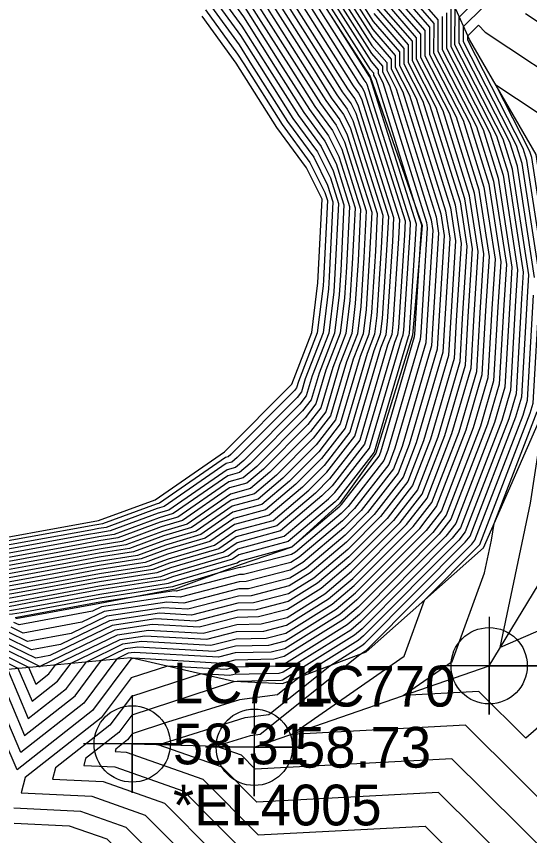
# Model space of a CAD drawing. Extents: x 2188792 to 2191981, y 386090 to 389710.
# Drawn here: x 2189631.5 to 2189663.1, y 387097.8 to 387148.1 of the extents above; entities that cross this region are included whole.
import ezdxf

# ---------------------------------------------------------------- set-up
doc = ezdxf.new("R2010")
doc.units = 0
for name, color, linetype in [('DTM Contours Major', 7, 'Continuous'), ('DTM Contours Minor', 7, 'Continuous'), ('Exist DTM Breakline', 7, 'Continuous'), ('Exist DTM Breakline Cogo Comment', 7, 'Continuous'), ('Exist DTM Breakline Cogo Elevation', 7, 'Continuous'), ('Exist DTM Breakline Cogo Number', 7, 'Continuous'), ('Exist DTM Breakline Cogo Point CELL', 7, 'Continuous'), ('PH Exist DTM Breakline', 7, 'Continuous')]:
    doc.layers.add(name, color=color, linetype=linetype)

msp = doc.modelspace()

# ---------------------------------------------------------------- linework, layer by layer
at = {"layer": 'DTM Contours Major'}
for points in [[(2189647.605, 387154.888), (2189653.356, 387145.845), (2189654.035, 387145.062), (2189654.034, 387144.713), (2189654.465, 387143.873), (2189657.034, 387135.639), (2189657.136, 387134.979), (2189656.746, 387128.839), (2189656.703, 387128.084), (2189654.801, 387121.603), (2189654.415, 387120.6), (2189652.316, 387117.904), (2189651.57, 387117.157), (2189648.909, 387114.911), (2189648.399, 387114.593), (2189645.491, 387113.849), (2189645.247, 387113.844), (2189641.36, 387112.838), (2189641.227, 387112.846), (2189639.101, 387112.531), (2189636.658, 387112.15), (2189631.567, 387111.212)], [(2189646.36, 387153.857), (2189652.258, 387144.532), (2189652.567, 387144.044), (2189652.792, 387143.738), (2189652.911, 387143.499), (2189655.42, 387135.563), (2189655.376, 387134.685), (2189655.01, 387129.027), (2189654.955, 387128.574), (2189654.773, 387128.103), (2189652.933, 387121.863), (2189650.94, 387119.302), (2189650.314, 387118.674), (2189647.766, 387116.527), (2189645.094, 387115.801), (2189644.261, 387115.224), (2189640.999, 387114.263), (2189640.165, 387113.955), (2189636.641, 387113.405), (2189632.825, 387112.703), (2189630.597, 387112.3)], [(2189645.921, 387150.976), (2189649.847, 387144.77), (2189650.886, 387143.129), (2189651.642, 387142.096), (2189652.045, 387141.291), (2189653.714, 387136.01), (2189653.599, 387133.704), (2189653.356, 387129.938), (2189653.195, 387128.618), (2189652.663, 387127.247), (2189651.438, 387123.094), (2189650.112, 387121.39), (2189648.312, 387119.583), (2189646.616, 387118.154), (2189644.838, 387117.671), (2189642.859, 387116.301), (2189640.688, 387115.661), (2189638.969, 387115.027), (2189636.623, 387114.661), (2189634.084, 387114.193), (2189629.733, 387113.407)], [(2189630.325, 387107.976), (2189632.033, 387103.97), (2189635.141, 387106.401), (2189636.772, 387108.588), (2189638.247, 387109.301), (2189638.986, 387109.41), (2189643.716, 387109.139), (2189645.006, 387109.473), (2189647.041, 387109.517), (2189648.064, 387109.779), (2189651.176, 387111.72), (2189652.376, 387112.732), (2189656.319, 387116.686), (2189657.357, 387118.019), (2189659.174, 387122.737), (2189660.169, 387126.128), (2189660.393, 387130.046), (2189660.605, 387133.372), (2189659.974, 387137.458), (2189658.576, 387141.941), (2189656.654, 387145.687), (2189656.657, 387147.247), (2189653.628, 387150.741)], [(2189644.006, 387150.136), (2189645.482, 387148.095), (2189647.435, 387145.008), (2189649.205, 387142.213), (2189650.493, 387140.455), (2189651.178, 387139.083), (2189652.009, 387136.456), (2189651.822, 387132.723), (2189651.701, 387130.85), (2189651.435, 387128.662), (2189650.553, 387126.391), (2189649.944, 387124.325), (2189649.284, 387123.477), (2189646.311, 387120.493), (2189645.467, 387119.782), (2189644.583, 387119.542), (2189641.458, 387117.378), (2189640.378, 387117.06), (2189637.772, 387116.098), (2189636.606, 387115.916), (2189635.343, 387115.684), (2189628.869, 387114.514)], [(2189653.492, 387148.293), (2189655.346, 387146.154), (2189655.344, 387145.2), (2189656.52, 387142.907), (2189658.504, 387136.548), (2189658.87, 387134.176), (2189658.57, 387129.442), (2189658.436, 387127.106), (2189656.988, 387122.17), (2189655.886, 387119.309), (2189654.317, 387117.295), (2189651.973, 387114.945), (2189650.042, 387113.315), (2189648.231, 387112.186), (2189646.266, 387111.683), (2189645.126, 387111.658), (2189642.538, 387110.989), (2189640.107, 387111.128), (2189637.427, 387110.731), (2189633.589, 387108.875), (2189632.724, 387108.712), (2189630.704, 387109.708)], [(2189657.968, 387148.339), (2189657.964, 387146.175), (2189660.631, 387140.974), (2189661.444, 387138.368), (2189662.339, 387132.568), (2189662.217, 387130.649), (2189661.903, 387125.151), (2189661.361, 387123.304), (2189658.829, 387116.729), (2189658.32, 387116.076), (2189652.779, 387110.52), (2189652.31, 387110.124), (2189647.897, 387107.371), (2189647.815, 387107.351), (2189645.1, 387107.292), (2189644.897, 387107.265), (2189644.755, 387107.221), (2189638.621, 387105.219), (2189637.821, 387104.147), (2189635.783, 387102.552), (2189635.675, 387102.136), (2189637.572, 387102.047), (2189641.816, 387100.554), (2189646.489, 387095.847)], [(2189659.274, 387146.662), (2189659.274, 387146.923), (2189659.943, 387147.587), (2189660.338, 387147.144), (2189666.223, 387143.262)], [(2189664.073, 387131.764), (2189662.914, 387139.278), (2189662.687, 387140.008), (2189659.274, 387146.662)], [(2189665.225, 387105.878), (2189662.851, 387103.796), (2189659.953, 387106.663), (2189655.312, 387106.421), (2189658.316, 387108.505), (2189660.313, 387113.953), (2189660.737, 387115.963), (2189660.891, 387116.975), (2189663.547, 387123.87)], [(2189631.567, 387111.212), (2189631.461, 387111.193)]]:
    msp.add_lwpolyline(points, dxfattribs=at)
at = {"layer": 'DTM Contours Minor'}
for points in [[(2189647.266, 387154.889), (2189653.329, 387145.355), (2189653.772, 387144.844), (2189653.772, 387144.615), (2189654.053, 387144.066), (2189656.74, 387135.457), (2189656.789, 387135.14), (2189656.381, 387128.718), (2189656.356, 387128.279), (2189654.364, 387121.49), (2189654.121, 387120.858), (2189651.915, 387118.026), (2189651.49, 387117.599), (2189648.682, 387115.23), (2189648.432, 387115.075), (2189645.336, 387114.282), (2189645.271, 387114.281), (2189643.923, 387113.932), (2189641.248, 387113.144), (2189641.122, 387113.098), (2189636.654, 387112.401), (2189631.819, 387111.51), (2189631.289, 387111.414), (2189623.717, 387110.905)], [(2189648.963, 387154.882), (2189653.465, 387147.803), (2189655.083, 387145.936), (2189655.082, 387145.103), (2189656.109, 387143.1), (2189658.21, 387136.366), (2189658.523, 387134.336), (2189658.205, 387129.322), (2189658.089, 387127.302), (2189656.551, 387122.057), (2189655.592, 387119.567), (2189653.917, 387117.417), (2189651.893, 387115.387), (2189649.816, 387113.635), (2189648.265, 387112.667), (2189646.111, 387112.116), (2189645.15, 387112.095), (2189642.302, 387111.358), (2189640.331, 387111.472), (2189637.263, 387111.017), (2189634.245, 387109.558), (2189632.467, 387109.223), (2189630.873, 387110.009)], [(2189648.624, 387154.884), (2189653.438, 387147.314), (2189654.821, 387145.717), (2189654.82, 387145.005), (2189655.698, 387143.293), (2189657.916, 387136.184), (2189658.177, 387134.497), (2189657.84, 387129.201), (2189657.743, 387127.497), (2189656.113, 387121.943), (2189655.298, 387119.825), (2189653.517, 387117.539), (2189651.812, 387115.83), (2189649.589, 387113.954), (2189648.298, 387113.149), (2189645.956, 387112.549), (2189645.174, 387112.533), (2189642.067, 387111.728), (2189640.555, 387111.815), (2189637.098, 387111.303), (2189634.902, 387110.241), (2189632.211, 387109.733), (2189631.041, 387110.31)], [(2189648.284, 387154.885), (2189653.41, 387146.824), (2189654.559, 387145.499), (2189654.558, 387144.908), (2189655.287, 387143.486), (2189657.622, 387136.002), (2189657.83, 387134.658), (2189657.475, 387129.08), (2189657.396, 387127.693), (2189655.676, 387121.83), (2189655.003, 387120.083), (2189653.116, 387117.66), (2189651.732, 387116.272), (2189649.362, 387114.273), (2189648.332, 387113.63), (2189645.801, 387112.983), (2189645.198, 387112.97), (2189641.831, 387112.098), (2189640.779, 387112.159), (2189636.934, 387111.589), (2189635.558, 387110.923), (2189631.954, 387110.244), (2189631.209, 387110.611)], [(2189647.945, 387154.886), (2189653.383, 387146.334), (2189654.297, 387145.281), (2189654.296, 387144.81), (2189654.876, 387143.68), (2189657.328, 387135.82), (2189657.483, 387134.819), (2189657.111, 387128.959), (2189657.049, 387127.888), (2189655.239, 387121.717), (2189654.709, 387120.341), (2189652.716, 387117.782), (2189651.651, 387116.714), (2189649.136, 387114.592), (2189648.365, 387114.112), (2189645.646, 387113.416), (2189645.223, 387113.407), (2189641.596, 387112.468), (2189641.003, 387112.502), (2189636.77, 387111.875), (2189636.215, 387111.606), (2189631.697, 387110.754), (2189631.378, 387110.912)], [(2189648.455, 387115.55), (2189648.778, 387115.822), (2189651.409, 387118.042), (2189651.515, 387118.148), (2189653.826, 387121.116), (2189653.927, 387121.377), (2189656.009, 387128.475), (2189656.016, 387128.597), (2189656.37, 387134.17), (2189656.442, 387135.273), (2189656.443, 387135.295), (2189656.214, 387136.018), (2189653.642, 387144.259), (2189653.51, 387144.518), (2189653.51, 387144.625), (2189653.301, 387144.866), (2189646.927, 387154.891)], [(2189630.77, 387112.079), (2189632.574, 387112.405), (2189636.644, 387113.154), (2189640.404, 387113.741), (2189641.061, 387113.983), (2189644.541, 387115.008), (2189645.145, 387115.426), (2189647.996, 387116.201), (2189650.714, 387118.492), (2189651.106, 387118.885), (2189653.232, 387121.616), (2189655.195, 387128.274), (2189655.307, 387128.565), (2189655.341, 387128.845), (2189655.731, 387134.881), (2189655.761, 387135.474), (2189653.085, 387143.94), (2189653.022, 387144.066), (2189652.903, 387144.227), (2189652.741, 387144.484), (2189646.448, 387154.433)], [(2189646.272, 387153.281), (2189651.776, 387144.579), (2189652.231, 387143.861), (2189652.562, 387143.409), (2189652.738, 387143.057), (2189655.078, 387135.653), (2189655.02, 387134.489), (2189654.679, 387129.209), (2189654.603, 387128.582), (2189654.351, 387127.932), (2189652.634, 387122.109), (2189650.775, 387119.72), (2189649.914, 387118.856), (2189647.536, 387116.852), (2189645.043, 387116.175), (2189643.981, 387115.439), (2189640.937, 387114.543), (2189639.926, 387114.169), (2189636.637, 387113.656), (2189633.077, 387113.001), (2189630.425, 387112.521)], [(2189630.252, 387112.743), (2189633.329, 387113.299), (2189636.634, 387113.908), (2189639.686, 387114.384), (2189640.875, 387114.822), (2189643.7, 387115.655), (2189644.992, 387116.549), (2189647.306, 387117.178), (2189649.513, 387119.038), (2189650.609, 387120.137), (2189652.335, 387122.355), (2189653.929, 387127.761), (2189654.251, 387128.591), (2189654.349, 387129.391), (2189654.665, 387134.292), (2189654.737, 387135.742), (2189652.565, 387142.616), (2189652.332, 387143.081), (2189651.895, 387143.678), (2189651.294, 387144.627), (2189646.185, 387152.705)], [(2189653.71, 387152.209), (2189657.443, 387147.902), (2189657.44, 387145.98), (2189659.809, 387141.361), (2189660.856, 387138.004), (2189661.645, 387132.889), (2189661.487, 387130.408), (2189661.209, 387125.542), (2189660.486, 387123.077), (2189658.24, 387117.245), (2189657.52, 387116.32), (2189652.618, 387111.405), (2189651.856, 387110.762), (2189647.964, 387108.334), (2189647.505, 387108.217), (2189644.933, 387108.161), (2189644.422, 387108.029), (2189640.823, 387108.236), (2189638.582, 387107.504), (2189636.749, 387105.049), (2189632.079, 387101.395), (2189631.831, 387100.44), (2189636.178, 387100.236), (2189639.448, 387099.085), (2189646.672, 387091.811)], [(2189658.75, 387146.467), (2189658.753, 387148.074), (2189662.88, 387152.179)], [(2189646.097, 387152.129), (2189650.811, 387144.675), (2189651.558, 387143.495), (2189652.102, 387142.753), (2189652.391, 387142.174), (2189654.396, 387135.831), (2189654.309, 387134.096), (2189654.018, 387129.574), (2189653.899, 387128.6), (2189653.507, 387127.589), (2189652.036, 387122.601), (2189650.444, 387120.555), (2189649.113, 387119.22), (2189647.076, 387117.503), (2189644.94, 387116.923), (2189643.42, 387115.87), (2189640.813, 387115.102), (2189639.447, 387114.598), (2189636.63, 387114.159), (2189633.581, 387113.597), (2189630.079, 387112.964)], [(2189653.683, 387151.72), (2189657.181, 387147.684), (2189657.178, 387145.882), (2189659.398, 387141.554), (2189660.562, 387137.822), (2189661.298, 387133.05), (2189661.123, 387130.287), (2189660.863, 387125.737), (2189660.049, 387122.963), (2189657.946, 387117.503), (2189657.119, 387116.442), (2189652.538, 387111.847), (2189651.629, 387111.081), (2189647.997, 387108.816), (2189647.351, 387108.65), (2189644.957, 387108.598), (2189644.187, 387108.399), (2189638.757, 387108.711), (2189638.562, 387108.647), (2189636.213, 387105.5), (2189631.571, 387101.868), (2189630.764, 387103.763)], [(2189653.655, 387151.23), (2189656.919, 387147.465), (2189656.916, 387145.785), (2189658.987, 387141.747), (2189660.268, 387137.64), (2189660.951, 387133.211), (2189660.758, 387130.167), (2189660.516, 387125.933), (2189659.612, 387122.85), (2189657.652, 387117.761), (2189656.719, 387116.564), (2189652.457, 387112.29), (2189651.403, 387111.4), (2189648.03, 387109.297), (2189647.196, 387109.084), (2189644.981, 387109.036), (2189643.951, 387108.769), (2189638.762, 387109.067), (2189638.411, 387109.015), (2189637.711, 387108.676), (2189635.677, 387105.951), (2189631.802, 387102.919), (2189629.744, 387107.748)], [(2189646.009, 387151.552), (2189650.329, 387144.722), (2189651.222, 387143.312), (2189651.872, 387142.424), (2189652.218, 387141.732), (2189654.055, 387135.921), (2189653.954, 387133.9), (2189653.687, 387129.756), (2189653.547, 387128.609), (2189653.085, 387127.418), (2189651.737, 387122.847), (2189650.278, 387120.972), (2189648.713, 387119.401), (2189646.846, 387117.829), (2189644.889, 387117.297), (2189643.14, 387116.086), (2189640.751, 387115.382), (2189639.208, 387114.812), (2189636.627, 387114.41), (2189633.832, 387113.895), (2189629.906, 387113.186)], [(2189645.833, 387150.4), (2189649.364, 387144.818), (2189650.55, 387142.946), (2189651.412, 387141.768), (2189651.871, 387140.849), (2189653.373, 387136.099), (2189653.243, 387133.508), (2189653.025, 387130.121), (2189652.843, 387128.626), (2189652.241, 387127.076), (2189651.139, 387123.34), (2189649.947, 387121.807), (2189647.912, 387119.765), (2189646.387, 387118.48), (2189644.787, 387118.045), (2189642.579, 387116.516), (2189640.626, 387115.941), (2189638.729, 387115.241), (2189636.62, 387114.912), (2189634.336, 387114.491), (2189629.561, 387113.628)], [(2189630.977, 387108.038), (2189632.263, 387105.02), (2189634.604, 387106.852), (2189635.833, 387108.499), (2189638.083, 387109.587), (2189639.211, 387109.754), (2189643.48, 387109.509), (2189645.03, 387109.91), (2189646.886, 387109.95), (2189648.097, 387110.26), (2189650.949, 387112.039), (2189652.296, 387113.175), (2189655.918, 387116.807), (2189657.063, 387118.277), (2189658.737, 387122.623), (2189659.823, 387126.324), (2189660.028, 387129.925), (2189660.258, 387133.533), (2189659.68, 387137.276), (2189658.164, 387142.134), (2189656.392, 387145.59), (2189656.395, 387147.028), (2189653.601, 387150.251)], [(2189643.793, 387149.733), (2189645.394, 387147.519), (2189646.952, 387145.056), (2189648.869, 387142.03), (2189650.263, 387140.126), (2189651.005, 387138.642), (2189651.667, 387136.546), (2189651.466, 387132.527), (2189651.37, 387131.032), (2189651.083, 387128.67), (2189650.131, 387126.219), (2189649.645, 387124.571), (2189649.118, 387123.895), (2189645.91, 387120.675), (2189645.237, 387120.108), (2189644.531, 387119.916), (2189641.177, 387117.593), (2189640.316, 387117.34), (2189637.533, 387116.313), (2189636.602, 387116.168), (2189635.594, 387115.982), (2189628.697, 387114.735)], [(2189645.746, 387149.824), (2189648.882, 387144.865), (2189650.213, 387142.763), (2189651.182, 387141.44), (2189651.698, 387140.408), (2189653.032, 387136.188), (2189652.888, 387133.312), (2189652.694, 387130.303), (2189652.491, 387128.635), (2189651.819, 387126.904), (2189650.84, 387123.586), (2189649.781, 387122.225), (2189647.512, 387119.947), (2189646.157, 387118.805), (2189644.736, 387118.419), (2189642.299, 387116.732), (2189640.564, 387116.221), (2189638.49, 387115.455), (2189636.616, 387115.163), (2189634.587, 387114.789), (2189629.388, 387113.85)], [(2189630.199, 387108.806), (2189631.629, 387108.101), (2189632.494, 387106.071), (2189634.068, 387107.303), (2189634.895, 387108.41), (2189637.919, 387109.873), (2189639.435, 387110.098), (2189643.245, 387109.879), (2189645.054, 387110.347), (2189646.731, 387110.383), (2189648.131, 387110.742), (2189650.723, 387112.358), (2189652.215, 387113.617), (2189655.518, 387116.929), (2189656.769, 387118.535), (2189658.3, 387122.51), (2189659.476, 387126.519), (2189659.664, 387129.804), (2189659.911, 387133.693), (2189659.386, 387137.094), (2189657.753, 387142.327), (2189656.13, 387145.492), (2189656.132, 387146.81), (2189653.574, 387149.761)], [(2189659.012, 387146.565), (2189659.014, 387147.498), (2189661.412, 387149.883)], [(2189643.58, 387149.33), (2189645.306, 387146.943), (2189646.47, 387145.104), (2189648.532, 387141.847), (2189650.033, 387139.798), (2189650.832, 387138.2), (2189651.326, 387136.635), (2189651.111, 387132.331), (2189651.039, 387131.214), (2189650.731, 387128.679), (2189649.709, 387126.048), (2189649.346, 387124.817), (2189648.953, 387124.312), (2189645.51, 387120.857), (2189645.007, 387120.433), (2189644.48, 387120.29), (2189640.897, 387117.809), (2189640.254, 387117.619), (2189637.294, 387116.527), (2189636.599, 387116.419), (2189635.846, 387116.28), (2189628.524, 387114.957)], [(2189645.658, 387149.248), (2189648.399, 387144.913), (2189649.877, 387142.579), (2189650.952, 387141.111), (2189651.525, 387139.966), (2189652.691, 387136.278), (2189652.532, 387133.115), (2189652.363, 387130.485), (2189652.139, 387128.644), (2189651.397, 387126.733), (2189650.541, 387123.832), (2189649.615, 387122.642), (2189647.111, 387120.129), (2189645.927, 387119.131), (2189644.685, 387118.793), (2189642.018, 387116.947), (2189640.502, 387116.5), (2189638.251, 387115.67), (2189636.613, 387115.414), (2189634.839, 387115.088), (2189629.215, 387114.071)], [(2189630.368, 387109.107), (2189632.281, 387108.163), (2189632.724, 387107.122), (2189633.532, 387107.754), (2189633.956, 387108.322), (2189637.755, 387110.159), (2189639.659, 387110.441), (2189643.009, 387110.249), (2189645.078, 387110.784), (2189646.576, 387110.817), (2189648.164, 387111.223), (2189650.496, 387112.677), (2189652.135, 387114.06), (2189655.118, 387117.051), (2189656.475, 387118.793), (2189657.862, 387122.397), (2189659.129, 387126.715), (2189659.299, 387129.684), (2189659.564, 387133.854), (2189659.092, 387136.912), (2189657.342, 387142.52), (2189655.868, 387145.395), (2189655.87, 387146.591), (2189653.546, 387149.272)], [(2189643.367, 387148.926), (2189645.219, 387146.367), (2189645.988, 387145.151), (2189648.196, 387141.664), (2189649.803, 387139.47), (2189650.658, 387137.759), (2189650.985, 387136.724), (2189650.756, 387132.134), (2189650.708, 387131.397), (2189650.379, 387128.688), (2189649.287, 387125.877), (2189649.047, 387125.063), (2189648.787, 387124.729), (2189645.11, 387121.039), (2189644.778, 387120.759), (2189644.429, 387120.664), (2189640.617, 387118.024), (2189640.191, 387117.899), (2189637.055, 387116.741), (2189636.595, 387116.67), (2189636.098, 387116.578), (2189628.351, 387115.178)], [(2189645.57, 387148.672), (2189647.917, 387144.961), (2189649.541, 387142.396), (2189650.723, 387140.783), (2189651.352, 387139.525), (2189652.35, 387136.367), (2189652.177, 387132.919), (2189652.032, 387130.668), (2189651.787, 387128.653), (2189650.975, 387126.562), (2189650.242, 387124.078), (2189649.45, 387123.06), (2189646.711, 387120.311), (2189645.697, 387119.456), (2189644.634, 387119.168), (2189641.738, 387117.163), (2189640.44, 387116.78), (2189638.012, 387115.884), (2189636.609, 387115.665), (2189635.091, 387115.386), (2189629.042, 387114.293)], [(2189653.519, 387148.782), (2189655.608, 387146.373), (2189655.606, 387145.297), (2189656.931, 387142.713), (2189658.798, 387136.73), (2189659.217, 387134.015), (2189658.934, 387129.563), (2189658.783, 387126.911), (2189657.425, 387122.283), (2189656.18, 387119.051), (2189654.718, 387117.173), (2189652.054, 387114.502), (2189650.269, 387112.996), (2189648.198, 387111.704), (2189646.421, 387111.25), (2189645.102, 387111.221), (2189642.773, 387110.619), (2189639.883, 387110.785), (2189637.591, 387110.445), (2189633.017, 387108.233), (2189632.996, 387108.205), (2189632.955, 387108.172), (2189632.932, 387108.225), (2189630.536, 387109.408)], [(2189643.154, 387148.523), (2189645.131, 387145.791), (2189645.505, 387145.199), (2189647.86, 387141.481), (2189649.573, 387139.141), (2189650.485, 387137.317), (2189650.644, 387136.814), (2189650.4, 387131.938), (2189650.377, 387131.579), (2189650.027, 387128.697), (2189648.865, 387125.706), (2189648.748, 387125.309), (2189648.621, 387125.147), (2189644.709, 387121.221), (2189644.548, 387121.084), (2189644.378, 387121.038), (2189640.336, 387118.24), (2189640.129, 387118.179), (2189636.815, 387116.956), (2189636.592, 387116.921), (2189636.35, 387116.876), (2189628.178, 387115.4)], [(2189658.23, 387148.558), (2189658.226, 387146.272), (2189661.042, 387140.781), (2189661.738, 387138.55), (2189662.686, 387132.407), (2189662.582, 387130.77), (2189662.249, 387124.955), (2189661.798, 387123.417), (2189659.123, 387116.471), (2189658.721, 387115.954), (2189652.86, 387110.078), (2189652.536, 387109.805), (2189648.936, 387107.559), (2189647.578, 387106.475), (2189645.24, 387106.169), (2189640.815, 387104.786), (2189638.641, 387104.076), (2189638.358, 387103.696), (2189637.635, 387103.131), (2189637.597, 387102.983), (2189638.269, 387102.952), (2189642.999, 387101.288), (2189646.398, 387097.865), (2189656.648, 387098.399), (2189674.627, 387080.612)], [(2189662.831, 387148.294), (2189667.63, 387145.128), (2189669.809, 387142.821), (2189680.313, 387132.407), (2189681.081, 387131.605), (2189684.866, 387130.133), (2189689.558, 387120.471), (2189692.997, 387116.023), (2189688.385, 387114.021), (2189671.258, 387102.79), (2189665.795, 387098), (2189659.127, 387104.597), (2189648.448, 387104.04), (2189655.359, 387108.837), (2189656.622, 387112.28), (2189659.922, 387115.589), (2189660.006, 387115.697), (2189663.11, 387123.757), (2189663.289, 387124.369), (2189663.676, 387131.132), (2189663.726, 387131.925), (2189662.62, 387139.096), (2189662.276, 387140.201), (2189659.012, 387146.565)], [(2189658.488, 387146.37), (2189658.492, 387148.65)], [(2189650.88, 387148.142), (2189653.223, 387144.436), (2189653.24, 387144.411), (2189653.252, 387144.394), (2189653.258, 387144.382), (2189656.102, 387135.385), (2189656.086, 387135.077), (2189655.672, 387128.662), (2189655.659, 387128.556), (2189655.617, 387128.446), (2189653.531, 387121.37), (2189651.272, 387118.468), (2189651.115, 387118.31), (2189648.226, 387115.875), (2189645.196, 387115.052), (2189644.822, 387114.793), (2189641.123, 387113.703), (2189640.643, 387113.526), (2189636.648, 387112.903), (2189632.322, 387112.106), (2189630.943, 387111.857)], [(2189657.706, 387148.121), (2189657.702, 387146.077), (2189660.22, 387141.168), (2189661.15, 387138.186), (2189661.992, 387132.729), (2189661.852, 387130.529), (2189661.556, 387125.346), (2189660.923, 387123.19), (2189658.534, 387116.987), (2189657.92, 387116.198), (2189652.699, 387110.963), (2189652.083, 387110.443), (2189647.93, 387107.853), (2189647.66, 387107.784), (2189644.909, 387107.724), (2189644.658, 387107.659), (2189642.889, 387107.761), (2189638.601, 387106.362), (2189637.285, 387104.598), (2189633.931, 387101.974), (2189633.753, 387101.288), (2189636.875, 387101.141), (2189640.632, 387099.819), (2189646.581, 387093.829)], [(2189702.211, 387112.776), (2189694.002, 387103.617), (2189683.326, 387096.616), (2189671.683, 387086.408), (2189657.474, 387100.465), (2189646.307, 387099.883), (2189644.183, 387102.022), (2189640.25, 387103.406), (2189645.583, 387105.072), (2189647.044, 387105.263), (2189650.788, 387108.254), (2189652.763, 387109.485), (2189652.94, 387109.635), (2189659.121, 387115.832), (2189659.417, 387116.213), (2189662.235, 387123.53), (2189662.596, 387124.76), (2189662.946, 387130.891), (2189663.032, 387132.246), (2189662.032, 387138.732), (2189661.453, 387140.588), (2189658.488, 387146.37)], [(2189663.379, 387132.086), (2189662.326, 387138.914), (2189661.864, 387140.395), (2189658.75, 387146.467)], [(2189663.098, 387139.815), (2189660.993, 387143.919), (2189664.817, 387141.396), (2189665.516, 387140.656), (2189670.642, 387135.574), (2189670.784, 387130.948), (2189677.871, 387129.045), (2189685.089, 387119.711), (2189661.269, 387109.37), (2189663.139, 387118.234), (2189664.018, 387123.993), (2189663.993, 387124.157), (2189664.405, 387131.374), (2189664.42, 387131.603), (2189663.208, 387139.46), (2189663.098, 387139.815)], [(2189668.739, 387092.204), (2189658.3, 387102.531), (2189646.216, 387101.901), (2189645.367, 387102.756), (2189643.795, 387103.309), (2189645.926, 387103.976), (2189646.511, 387104.052), (2189652.64, 387108.948), (2189652.99, 387109.166), (2189653.021, 387109.193), (2189659.521, 387115.711), (2189659.711, 387115.955), (2189662.673, 387123.644), (2189662.943, 387124.564), (2189663.311, 387131.012)], [(2189631.116, 387111.636), (2189632.07, 387111.808), (2189636.651, 387112.652), (2189640.883, 387113.312), (2189641.186, 387113.424), (2189645.102, 387114.578), (2189645.247, 387114.678), (2189648.455, 387115.55)], [(2189631.379, 387099.523), (2189635.481, 387099.33), (2189638.265, 387098.351), (2189646.763, 387089.793), (2189653.343, 387090.136), (2189675.534, 387068.182), (2189677.293, 387065.514), (2189673.661, 387049.813), (2189672.535, 387047.306), (2189658.509, 387033.907)], [(2189631.399, 387098.584), (2189634.784, 387098.425), (2189637.081, 387097.617), (2189646.854, 387087.775), (2189652.517, 387088.07), (2189671.614, 387069.177), (2189674.484, 387064.824), (2189671.509, 387051.964), (2189669.647, 387047.819), (2189657.721, 387036.426), (2189645.777, 387026.074)]]:
    msp.add_lwpolyline(points, dxfattribs=at)
at = {"layer": 'Exist DTM Breakline'}
msp.add_lwpolyline([(2189638.652, 387103.449), (2189646.155, 387103.245), (2189660.588, 387108.25), (2189671.434, 387126.078)], dxfattribs=at)
at = {"layer": 'Exist DTM Breakline Cogo Point CELL'}
for points in [[(2189660.588, 387111.25), (2189660.588, 387105.25), (2189660.588, 387108.25), (2189663.588, 387108.25), (2189657.588, 387108.25)], [(2189638.652, 387106.449), (2189638.652, 387100.449), (2189638.652, 387103.449), (2189641.652, 387103.449), (2189635.652, 387103.449)], [(2189646.155, 387106.245), (2189646.155, 387100.245), (2189646.155, 387103.245), (2189649.155, 387103.245), (2189643.155, 387103.245)]]:
    msp.add_lwpolyline(points, dxfattribs=at)
for centre in [(2189660.588, 387108.25), (2189638.652, 387103.449), (2189646.155, 387103.245)]:
    msp.add_circle(centre, 2.344, dxfattribs=at)
at = {"layer": 'PH Exist DTM Breakline'}
for points in [[(2189646.518, 387154.892), (2189653.277, 387144.431), (2189656.469, 387135.289), (2189655.875, 387128.551), (2189653.62, 387121.297), (2189651.383, 387118.188), (2189648.465, 387115.537), (2189645.28, 387114.441), (2189641.292, 387112.945), (2189636.659, 387112.069), (2189631.504, 387111.138)], [(2189629.701, 387107.916), (2189632.967, 387108.229), (2189638.56, 387108.756), (2189644.886, 387107.302), (2189647.882, 387107.164), (2189653.038, 387109.098), (2189660.239, 387115.492), (2189663.976, 387123.981), (2189664.703, 387131.472), (2189663.486, 387139.632), (2189659.375, 387146.7), (2189658.451, 387148.742)], [(2189628.014, 387115.61), (2189636.588, 387117.159), (2189640.07, 387118.444), (2189644.33, 387121.393), (2189648.464, 387125.543), (2189649.693, 387128.705), (2189650.063, 387131.752), (2189650.321, 387136.898), (2189649.355, 387138.83), (2189647.541, 387141.307), (2189645.047, 387145.244), (2189642.952, 387148.141)]]:
    msp.add_lwpolyline(points, dxfattribs=at)

# ---------------------------------------------------------------- texts
at = {"layer": 'Exist DTM Breakline Cogo Comment'}
msp.add_text('*EL4005', height=2.5, dxfattribs=at).set_placement((2189641.152, 387098.449))
at = {"layer": 'Exist DTM Breakline Cogo Elevation'}
for s, p in [('58.31', (2189641.152, 387102.199)), ('58.73', (2189648.655, 387101.995))]:
    msp.add_text(s, height=2.5, dxfattribs=at).set_placement(p)
at = {"layer": 'Exist DTM Breakline Cogo Number'}
for s, p in [('LC771', (2189641.152, 387105.949)), ('LC770', (2189648.655, 387105.745))]:
    msp.add_text(s, height=2.5, dxfattribs=at).set_placement(p)

doc.saveas('drawing.dxf')
